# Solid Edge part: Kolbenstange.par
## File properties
Username: ahadarics
Dokumentum tartalom típus: 0
Author: ahadarics
Last saved by: ahadarics
Revision: 87
Sűrűség: 0,000 kg/m^3
Pontosság: 0,990
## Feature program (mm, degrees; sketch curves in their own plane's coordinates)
base feature "unnamed BaseFeature 1"
sketch for "unnamed Protrusion 1" plane through (64, 0, 0) normal (1, 0, 0) x-axis (0, 1, 0)
  circle centre (0, 0) radius 12.5
extrude "unnamed Protrusion 1" add finite 33 along -normal
thread "Menet_2"  ThreadDepth = 22 mm
chamfer "Letörés_1" setback 0.7
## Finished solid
Body 1: solid body, 13 faces, 23 edges, 12 vertices.
  Faces by surface: plane 9, cylinder 3, cone 1
  Edges by curve: line 12, circle 11
Bounding box of the edges (mm): 420.500 x 25.000 x 25.000, from (-356.5, -12.5, -12.5) to (64, 12.5, 12.5).
Cylindrical faces by radius (mm): R5 x2, R12.5 x1
Conical faces (half-angle, radius in mm at the cone's reference point): 45 deg R4.3 x1
Planar faces by outward normal: +x 3, +z 1, -x 4, -z 1
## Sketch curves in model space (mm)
circle centre (64, 0, 0) radius 12.5
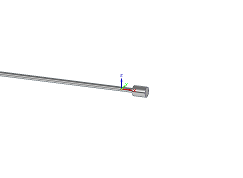
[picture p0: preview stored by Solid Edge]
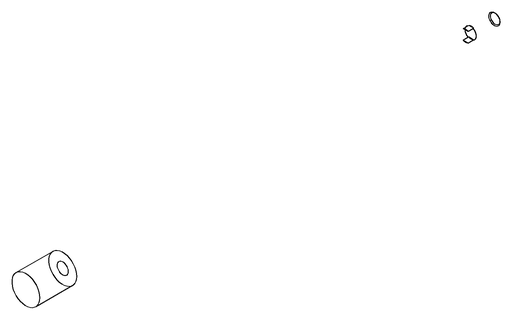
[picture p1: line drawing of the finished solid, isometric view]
